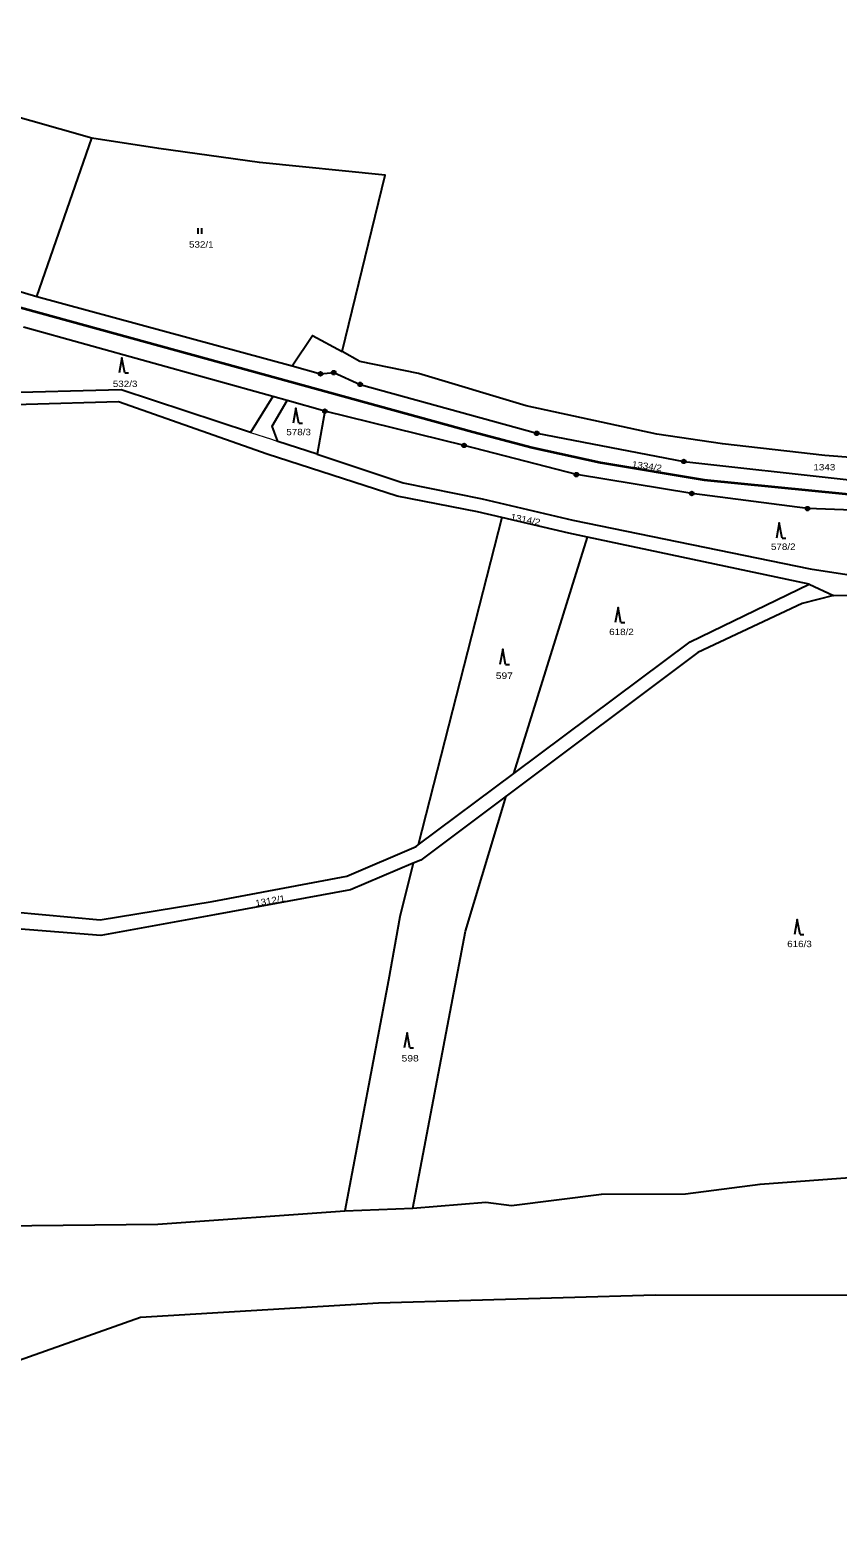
# Model space of a CAD drawing. Extents: x -872229 to -869198, y -1075981 to -1074329.
# Drawn here: x -869759.2 to -869544.7, y -1075719.7 to -1075319.4 of the extents above; entities that cross this region are included whole.
import ezdxf

# ---------------------------------------------------------------- set-up
doc = ezdxf.new("R2010")
doc.units = 0
doc.header["$LTSCALE"] = 0.68
for name, color, linetype, lineweight in [('1', 7, 'Continuous', 25), ('3', 7, 'Continuous', 25), ('4', 7, 'Continuous', 13), ('6', 7, 'Continuous', 25), ('8', 7, 'Continuous', 25)]:
    doc.layers.add(name, color=color, linetype=linetype, lineweight=lineweight)
doc.layers.add('2', color=7, linetype='Continuous')

msp = doc.modelspace()

# ---------------------------------------------------------------- linework, layer by layer
at = {"layer": '1'}
for p, q in [((-869757.47, -1075390.06), (-869689.66, -1075408.53)), ((-869694.77, -1075416.68), (-869760.99, -1075398.24)), ((-869689.66, -1075408.53), (-869682.1, -1075410.63)), ((-869680.93, -1075420.53), (-869690.98, -1075417.73)), ((-869682.99, -1075432.01), (-869693.4, -1075428.58)), ((-869552.3, -1075466.48), (-869611.2, -1075454.02)), ((-869552.3, -1075466.48), (-869545.81, -1075469.48)), ((-869656.72, -1075536.14), (-869656.16, -1075535.72))]:
    msp.add_line(p, q, dxfattribs=at)
for points in [[(-869742.8, -1075348.02), (-869767.51, -1075341.02), (-869775.27, -1075338.64), (-869785.4, -1075334.51), (-869794.46, -1075328.86), (-869803.48, -1075319.37), (-869813.74, -1075351.24), (-869816.07, -1075356.1), (-869821.67, -1075367.58)], [(-869821.67, -1075367.58), (-869823.79, -1075372.09), (-869775.47, -1075384.75), (-869757.47, -1075390.06), (-869742.8, -1075348.02)], [(-869676.3, -1075404.74), (-869664.95, -1075357.91), (-869698.26, -1075354.49), (-869725.06, -1075350.77), (-869742.8, -1075348.02)], [(-869689.66, -1075408.53), (-869684.2, -1075400.47), (-869676.3, -1075404.74)], [(-869470.63, -1075431.72), (-869482.67, -1075433.38), (-869492.77, -1075434.3), (-869516.25, -1075434.78), (-869548.16, -1075432.33), (-869575.31, -1075429.18), (-869592.79, -1075426.68), (-869627.42, -1075419.15), (-869656.02, -1075410.53), (-869671.66, -1075407.34), (-869676.3, -1075404.74)], [(-869633.9, -1075448.79), (-869640.35, -1075447.27), (-869661.71, -1075443.1), (-869696.29, -1075431.95), (-869735.78, -1075418.09), (-869784.91, -1075419.45), (-869829.22, -1075413.77), (-869837.88, -1075413.34), (-869849.23, -1075414.84), (-869864.5, -1075417.75), (-869881.67, -1075417.62), (-869942.3, -1075409.15)], [(-869682.1, -1075410.63), (-869678.59, -1075410.32), (-869671.56, -1075413.43), (-869624.66, -1075426.43), (-869585.55, -1075433.9), (-869542.43, -1075438.72), (-869516.5, -1075439.44), (-869471.65, -1075436.24), (-869470.63, -1075431.72)], [(-869693.4, -1075428.58), (-869694.91, -1075424.51), (-869690.98, -1075417.73), (-869694.77, -1075416.68), (-869700.66, -1075426.2), (-869735.08, -1075414.89), (-869768.68, -1075415.77)], [(-869474.41, -1075449.19), (-869490.49, -1075448.38), (-869521.65, -1075447.59), (-869552.7, -1075446.43), (-869583.47, -1075442.4), (-869614.13, -1075437.41), (-869643.97, -1075429.64), (-869680.93, -1075420.53), (-869682.99, -1075432.01), (-869660.1, -1075439.54)], [(-869660.1, -1075439.54), (-869639.17, -1075443.87), (-869615.03, -1075449.51), (-869552.02, -1075462.41), (-869529.57, -1075465.84), (-869493.81, -1075464.4), (-869478.29, -1075465.32)], [(-869633.9, -1075448.79), (-869656.16, -1075535.72), (-869630.72, -1075516.75), (-869611.2, -1075454.02)], [(-869611.2, -1075454.02), (-869616.15, -1075452.97), (-869633.9, -1075448.79)], [(-869545.81, -1075469.48), (-869554.14, -1075471.6), (-869581.84, -1075484.64), (-869632.77, -1075522.77)], [(-869630.72, -1075516.75), (-869583.91, -1075481.84), (-869552.3, -1075466.48)], [(-869545.81, -1075469.48), (-869530, -1075469.33), (-869493.67, -1075469.07), (-869478.21, -1075470.13)], [(-869657.56, -1075632.18), (-869643.6, -1075558.66), (-869632.77, -1075522.77)], [(-869632.77, -1075522.77), (-869655.47, -1075539.76), (-869657.44, -1075540.59)], [(-869889.5, -1075592.13), (-869867.84, -1075583.27), (-869849.28, -1075576.32), (-869795.03, -1075560.97), (-869771.51, -1075552.75), (-869740.67, -1075555.67), (-869710.85, -1075550.74), (-869675.12, -1075544), (-869656.72, -1075536.14)], [(-869657.44, -1075540.59), (-869674.12, -1075547.66), (-869710.28, -1075554.3), (-869740.46, -1075559.8), (-869770.69, -1075557.44), (-869794.04, -1075564.75), (-869848.43, -1075580.14), (-869866.49, -1075586.59), (-869887.81, -1075595.64), (-869900.72, -1075605.56)], [(-869657.44, -1075540.59), (-869661, -1075554.81), (-869664.03, -1075571.68), (-869675.65, -1075632.94), (-869657.56, -1075632.18)], [(-869657.56, -1075632.18), (-869638.2, -1075630.62), (-869631.37, -1075631.49), (-869607.48, -1075628.49), (-869585.13, -1075628.43), (-869565.34, -1075625.83), (-869510.48, -1075621.78), (-869497.7, -1075618.94), (-869485.54, -1075612.97), (-869477.1, -1075605.86)], [(-869895.39, -1075719.74), (-869729.92, -1075661.11), (-869666.68, -1075657.35), (-869593.09, -1075655.24), (-869520.45, -1075655.26), (-869463.49, -1075641.67), (-869392.24, -1075631.04), (-869390.16, -1075631.43)], [(-869767.28, -1075640.08), (-869767.22, -1075636.85), (-869725.35, -1075636.46), (-869675.65, -1075632.94)]]:
    msp.add_lwpolyline(points, dxfattribs=at)
at = {"layer": '3'}
for p, q in [((-869714.621, -1075373.44), (-869714.621, -1075371.94)), ((-869713.62, -1075373.44), (-869713.62, -1075371.94)), ((-869734.11, -1075410.39), (-869733.114, -1075410.39)), ((-869687.86, -1075423.72), (-869686.864, -1075423.72)), ((-869559.49, -1075454.24), (-869558.494, -1075454.24)), ((-869602.28, -1075476.66), (-869601.284, -1075476.66)), ((-869632.92, -1075487.78), (-869631.924, -1075487.78)), ((-869554.71, -1075559.56), (-869553.714, -1075559.56)), ((-869658.36, -1075589.66), (-869657.364, -1075589.66))]:
    msp.add_line(p, q, dxfattribs=at)
for points in [[(-869734.11, -1075410.39), (-869734.86, -1075406.39), (-869735.61, -1075410.39)], [(-869687.86, -1075423.72), (-869688.61, -1075419.72), (-869689.36, -1075423.72)], [(-869559.49, -1075454.24), (-869560.24, -1075450.24), (-869560.99, -1075454.24)], [(-869602.28, -1075476.66), (-869603.03, -1075472.66), (-869603.78, -1075476.66)], [(-869632.92, -1075487.78), (-869633.67, -1075483.78), (-869634.42, -1075487.78)], [(-869554.71, -1075559.56), (-869555.46, -1075555.56), (-869556.21, -1075559.56)], [(-869658.36, -1075589.66), (-869659.11, -1075585.66), (-869659.86, -1075589.66)]]:
    msp.add_lwpolyline(points, dxfattribs=at)
at = {"layer": '4'}
msp.add_lwpolyline([(-869700.66, -1075426.2), (-869695.14, -1075428.01), (-869693.4, -1075428.58)], dxfattribs=at)
at = {"layer": '6', "lineweight": 35}
msp.add_lwpolyline([(-869860.88, -1075365.74), (-869846.01, -1075369.94), (-869704.43, -1075408.78), (-869641.66, -1075426.07), (-869625.84, -1075430.18), (-869607.72, -1075434.15), (-869580.2, -1075438.82), (-869542.66, -1075442.5), (-869518.18, -1075443.57), (-869485.71, -1075443.04), (-869459.17, -1075441.98), (-869409.77, -1075437.63)], dxfattribs=at)
at = {"layer": '8'}
for centre, radius in [((-869678.59, -1075410.3199), 0.5), ((-869682.1, -1075410.6299), 0.5), ((-869682.1, -1075410.6299), 0.0303), ((-869678.59, -1075410.3199), 0.0303), ((-869671.56, -1075413.4299), 0.5), ((-869671.56, -1075413.4299), 0.0303), ((-869680.93, -1075420.5299), 0.5), ((-869680.93, -1075420.5299), 0.0303), ((-869643.97, -1075429.6399), 0.5), ((-869643.97, -1075429.6399), 0.0303), ((-869624.66, -1075426.4299), 0.5), ((-869624.66, -1075426.4299), 0.0303), ((-869585.55, -1075433.8999), 0.5), ((-869614.13, -1075437.4099), 0.5), ((-869614.13, -1075437.4099), 0.0303), ((-869585.55, -1075433.8999), 0.0303), ((-869583.47, -1075442.3999), 0.5), ((-869583.47, -1075442.3999), 0.0303), ((-869552.7, -1075446.4299), 0.5), ((-869552.7, -1075446.4299), 0.0303)]:
    msp.add_circle(centre, radius, dxfattribs=at)

# ---------------------------------------------------------------- texts
at = {"layer": '2'}
for s, width, p in [('532/1', 1.15, (-869717.03, -1075377.12)), ('532/3', 1.15, (-869737.27, -1075414.14)), ('578/3', 1.15, (-869691.18, -1075426.94)), ('1343', 1.15, (-869551.16, -1075436.28)), ('578/2', 1.15, (-869562.44, -1075457.39)), ('618/2', 1.15, (-869605.41, -1075480.01)), ('597', 1.2, (-869635.53, -1075491.64)), ('616/3', 1.15, (-869558.12, -1075562.88)), ('598', 1.2, (-869660.55, -1075593.24))]:
    msp.add_text(s, height=1.7, dxfattribs=dict(at, width=width)).set_placement(p)
at = {"layer": '2', "width": 1.15}
for s, rotation, p in [('1334/2', 352, (-869599.448, -1075435.411)), ('1314/2', 349, (-869631.722, -1075449.404)), ('1312/1', 10, (-869699.262, -1075552.087))]:
    msp.add_text(s, height=1.7, rotation=rotation, dxfattribs=at).set_placement(p)

doc.saveas('drawing.dxf')
